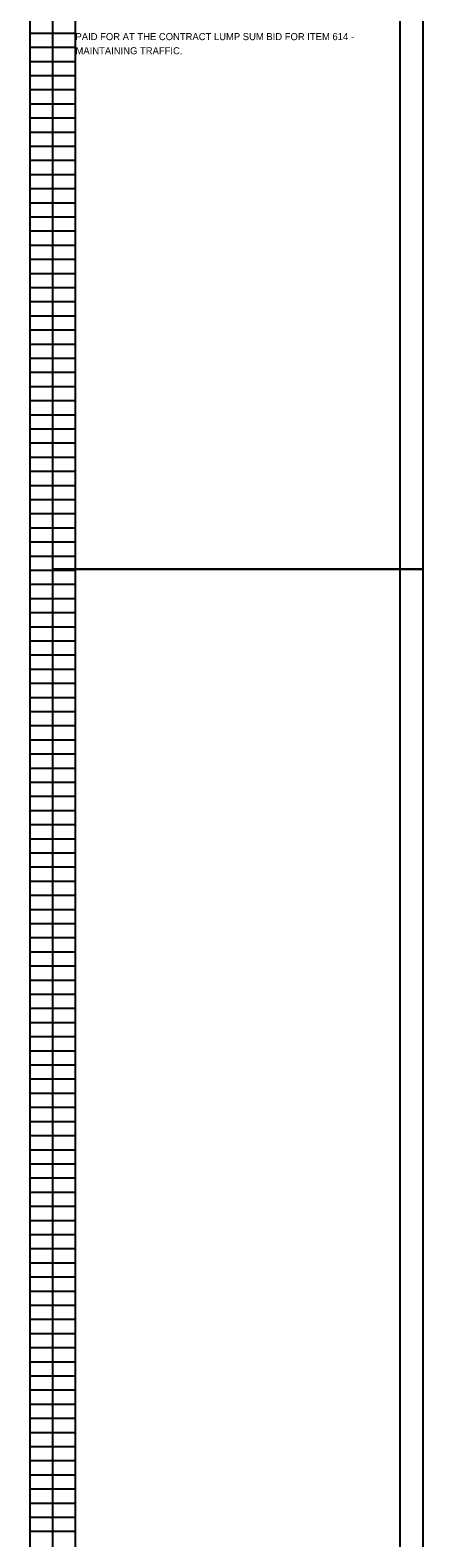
# Model space of a CAD drawing. Extents: x 0 to 19, y -301 to 22.
# Drawn here: x 1.5 to 9.29, y -139.15 to -109.28 of the extents above; entities that cross this region are included whole.
import ezdxf

# ---------------------------------------------------------------- set-up
doc = ezdxf.new("R2010")
doc.units = 0
doc.layers.add('SC_Scratch1', color=7, linetype='Continuous')
doc.layers.add('SH_Text', color=7, linetype='Continuous')

msp = doc.modelspace()

# ---------------------------------------------------------------- linework, layer by layer
at = {"layer": 'SC_Scratch1'}
for p, q in [((1.5, -119.98), (1.5, -99.82)), ((2.4, -119.98), (2.4, -99.82)), ((8.84, -119.98), (8.84, -99.82)), ((1.5, -109.34), (2.4, -109.34)), ((1.5, -109.62), (2.4, -109.62)), ((1.5, -109.9), (2.4, -109.9)), ((1.5, -110.18), (2.4, -110.18)), ((1.5, -110.46), (2.4, -110.46)), ((1.5, -110.74), (2.4, -110.74)), ((1.5, -111.02), (2.4, -111.02)), ((1.5, -111.3), (2.4, -111.3)), ((1.5, -111.58), (2.4, -111.58)), ((1.5, -111.86), (2.4, -111.86)), ((1.5, -112.14), (2.4, -112.14)), ((1.5, -112.42), (2.4, -112.42)), ((1.5, -112.7), (2.4, -112.7)), ((1.5, -112.98), (2.4, -112.98)), ((1.5, -113.26), (2.4, -113.26)), ((1.5, -113.54), (2.4, -113.54)), ((1.5, -113.82), (2.4, -113.82)), ((1.5, -114.1), (2.4, -114.1)), ((1.5, -114.38), (2.4, -114.38)), ((1.5, -114.66), (2.4, -114.66)), ((1.5, -114.94), (2.4, -114.94)), ((1.5, -115.22), (2.4, -115.22)), ((1.5, -115.5), (2.4, -115.5)), ((1.5, -115.78), (2.4, -115.78)), ((1.5, -116.06), (2.4, -116.06)), ((1.5, -116.34), (2.4, -116.34)), ((1.5, -116.62), (2.4, -116.62)), ((1.5, -116.9), (2.4, -116.9)), ((1.5, -117.18), (2.4, -117.18)), ((1.5, -117.46), (2.4, -117.46)), ((1.5, -117.74), (2.4, -117.74)), ((1.5, -118.02), (2.4, -118.02)), ((1.5, -118.3), (2.4, -118.3)), ((1.5, -118.58), (2.4, -118.58)), ((1.5, -118.86), (2.4, -118.86)), ((1.5, -119.14), (2.4, -119.14)), ((1.5, -119.42), (2.4, -119.42)), ((1.5, -119.7), (2.4, -119.7)), ((1.5, -119.98), (2.4, -119.98)), ((1.5, -119.98), (2.4, -119.98)), ((1.5, -140.14), (1.5, -119.98)), ((2.4, -140.14), (2.4, -119.98)), ((8.84, -140.14), (8.84, -119.98)), ((1.5, -120.26), (2.4, -120.26)), ((1.5, -120.54), (2.4, -120.54)), ((1.5, -120.82), (2.4, -120.82)), ((1.5, -121.1), (2.4, -121.1)), ((1.5, -121.38), (2.4, -121.38)), ((1.5, -121.66), (2.4, -121.66)), ((1.5, -121.94), (2.4, -121.94)), ((1.5, -122.22), (2.4, -122.22)), ((1.5, -122.5), (2.4, -122.5)), ((1.5, -122.78), (2.4, -122.78)), ((1.5, -123.06), (2.4, -123.06)), ((1.5, -123.34), (2.4, -123.34)), ((1.5, -123.62), (2.4, -123.62)), ((1.5, -123.9), (2.4, -123.9)), ((1.5, -124.18), (2.4, -124.18)), ((1.5, -124.46), (2.4, -124.46)), ((1.5, -124.74), (2.4, -124.74)), ((1.5, -125.02), (2.4, -125.02)), ((1.5, -125.3), (2.4, -125.3)), ((1.5, -125.58), (2.4, -125.58)), ((1.5, -125.86), (2.4, -125.86)), ((1.5, -126.14), (2.4, -126.14)), ((1.5, -126.42), (2.4, -126.42)), ((1.5, -126.7), (2.4, -126.7)), ((1.5, -126.98), (2.4, -126.98)), ((1.5, -127.26), (2.4, -127.26)), ((1.5, -127.54), (2.4, -127.54)), ((1.5, -127.82), (2.4, -127.82)), ((1.5, -128.1), (2.4, -128.1)), ((1.5, -128.38), (2.4, -128.38)), ((1.5, -128.66), (2.4, -128.66)), ((1.5, -128.94), (2.4, -128.94)), ((1.5, -129.22), (2.4, -129.22)), ((1.5, -129.5), (2.4, -129.5)), ((1.5, -129.78), (2.4, -129.78)), ((1.5, -130.06), (2.4, -130.06)), ((1.5, -130.34), (2.4, -130.34)), ((1.5, -130.62), (2.4, -130.62)), ((1.5, -130.9), (2.4, -130.9)), ((1.5, -131.18), (2.4, -131.18)), ((1.5, -131.46), (2.4, -131.46)), ((1.5, -131.74), (2.4, -131.74)), ((1.5, -132.02), (2.4, -132.02)), ((1.5, -132.3), (2.4, -132.3)), ((1.5, -132.58), (2.4, -132.58)), ((1.5, -132.86), (2.4, -132.86)), ((1.5, -133.14), (2.4, -133.14)), ((1.5, -133.42), (2.4, -133.42)), ((1.5, -133.7), (2.4, -133.7)), ((1.5, -133.98), (2.4, -133.98)), ((1.5, -134.26), (2.4, -134.26)), ((1.5, -134.54), (2.4, -134.54)), ((1.5, -134.82), (2.4, -134.82)), ((1.5, -135.1), (2.4, -135.1)), ((1.5, -135.38), (2.4, -135.38)), ((1.5, -135.66), (2.4, -135.66)), ((1.5, -135.94), (2.4, -135.94)), ((1.5, -136.22), (2.4, -136.22)), ((1.5, -136.5), (2.4, -136.5)), ((1.5, -136.78), (2.4, -136.78)), ((1.5, -137.06), (2.4, -137.06)), ((1.5, -137.34), (2.4, -137.34)), ((1.5, -137.62), (2.4, -137.62)), ((1.5, -137.9), (2.4, -137.9)), ((1.5, -138.18), (2.4, -138.18)), ((1.5, -138.46), (2.4, -138.46)), ((1.5, -138.74), (2.4, -138.74)), ((1.5, -139.02), (2.4, -139.02))]:
    msp.add_line(p, q, dxfattribs=at)
for points in [[(1.95, -99.803), (9.29, -99.803), (9.29, -119.963), (1.95, -119.963)], [(1.95, -119.963), (9.29, -119.963), (9.29, -140.123), (1.95, -140.123)]]:
    msp.add_lwpolyline(points, close=True, dxfattribs=at)

# ---------------------------------------------------------------- texts
at = {"layer": 'SH_Text'}
for s, p in [('PAID FOR AT THE CONTRACT LUMP SUM BID FOR ITEM 614 - ', (2.4, -109.48)), ('MAINTAINING TRAFFIC.', (2.4, -109.76))]:
    msp.add_text(s, height=0.14, dxfattribs=at).set_placement(p)

doc.saveas('drawing.dxf')
